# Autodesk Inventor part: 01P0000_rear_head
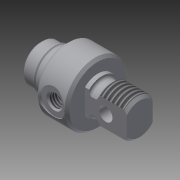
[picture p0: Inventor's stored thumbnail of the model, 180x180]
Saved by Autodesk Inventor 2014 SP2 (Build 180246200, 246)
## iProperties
Created: 2020-01
Part Number: 01P0000_rear_head
Material: Generic
Catalog Web Link: www.cadenas.de
Description: Rear Head-Original Line - Standard Air Cylinders
Vendor: BIMBA
Document SubType Name: Modeling
Designer: psadmin
Manufacturer: BIMBA
Mass: 3.86005 g
Surface Area: 22.3376 cm^2
Volume: 3.86005 cm^3
Density: 1 g/cm^3
Appearance: PSOLRGB-211-211-211
Category: PARTsolutions
Company: BIMBA
Title: 01P0000_rear_head
Author: Cadenas PARTsolutions
Comments: Original Line - Standard Air Cylinders
PSOL_IDENT_0: {$CADENAS_DATA\23d-libs\bimba\bimba_brand\bimba_imperial\bimba_full_line\original_line_cylinders\sta
PSOL_IDENT_1: ndard_air_cylinders\rear_head.prj},239 {VTYP=3D},{NB=01P0000_rear_head},{LINA=01P0000_rear_head},{NN=
PSOL_IDENT_2: Rear Head},{DATE=23.12.2019 10:40:48},{GEOMDATE=15.10.2019 12:00:43},{VERSION=},{LINEID=20},{WBVAR=M
PSOL_IDENT_3: NT,ACTING,DER,Q,T1,T2,T3,T4,TRIM,Y,K,MB,CUSH,FBON},{WBNUMERIC=TRIM,MB,CUSH}  {NB=01P0000_rear_head},
PSOL_IDENT_4: {LINA=01P0000_rear_head},{KT=DUMMY},{PN=01P0000},{BORE=0.43750},{BOREPN=01},{MNT=P},{MNTALG='' , 'Fr
PSOL_IDENT_5: ont Nose' , 'P' , 'Rear Pivot' , 'DX' , 'Double End' , 'BR' , 'Rear Block' , 'BRT' , 'Rear Trunnion'
PSOL_IDENT_6: },{ACTING=},{ACTINGALG= '' , 'Single Acting' },{DER=},{DERALG= '' , 'Standard' },{Q=},{T1=},{T2=},{T
PSOL_IDENT_7: 3=},{T4=},{TRIM=0},{Y=},{K=},{KALG= '', 'without K', 'K', 'with K' },{MB=0},{A1=1.1880},{A1N=0.5000}
PSOL_IDENT_8: ,{A1P=1.1880},{A1B=0.8120},{A1S=0.0000},{A2=0.188},{A2N=0.1880},{A3=0.0200},{D1=0.7380},{D1N=0.4855}
PSOL_IDENT_9: ,{D1P=0.7380},{D1B=0.4855},{D2=0.4465},{C1=0.0300},{C2=0.0300},{NDM=0.1900},{TAB=UNF},{NDMDP=0.2000}
PSOL_IDENT_10: ,{D3=0.1600},{A4=0.1880},{A5=0.3700},{D4=0.0000},{A6=0.0000},{A7=0.5000},{A8=0.1250},{D5=0.4855},{D6=
PSOL_IDENT_11: 0.1875},{A9=0.6250},{NDM2=0.4375},{TAB2=UNF},{C11=0.0300},{C22=0.0000},{C33=0.0300},{C44=0.0300},{A1
PSOL_IDENT_12: 0=0.3095},{A11=0.0000},{NDM3=0.1900},{NDM3N=0.1900},{NDM3B=0.1900},{TAB3=UNF},{TAB3N=UNF},{TAB3B=UNF
PSOL_IDENT_13: },{A12=0.5},{A12N=0.5000},{A12B=0.4680},{A13=0.9380},{D7=0.1590},{D8=0.4350},{A14=0.0500},{A15=0.077
PSOL_IDENT_14: 5},{D9=0.3600},{R1=0.0315},{X1=0.0000},{X2=0.0000},{CX=0.0000},{CC=0.0000},{CON=1},{S1=0.7500},{DB=0
PSOL_IDENT_15: .1562},{X1B=0.2500},{X2B=0.0620},{A8B=0.1250},{A9B=0.5620},{MODEL=1},{NDM4=0.1640},{TAB4=UNC},{NDM4D
PSOL_IDENT_16: P=0.2500},{BC=0.7500},{B1=0.5620},{B2=0.2500},{B3=0.3740},{ON=0},{ON2=1},{G1=0.0000},{G2=0.0000},{G3=
PSOL_IDENT_17: 0.0000},{G4=0.0000},{GD=0.0000},{G5=0.0000},{G6=0.0000},{RON=0},{H1=0.0000},{H2=0.0000},{H3=0.0000},
PSOL_IDENT_18: {H4=0.0000},{H5=0.0000},{H6=0.0000},{F=0.0000},{PNUT=0.7380},{CUSH=0},{CC11=0.000},{CC111=0.0000},{C
PSOL_IDENT_19: C22=0.0000},{CC33=0.0000},{CC44=0.0000},{CC55=0.0000},{CD1=0.0000},{CD2=0.0000},{CD3=0.0000},{CNDM3=
PSOL_IDENT_20: 0.0000},{CTAB3=0.0000},{OLEN=0.9380},{OD=0.2185},{STDIS=0.0000},{STDIS1=0.0000},{BUSHCON=D-8597},{BU
PSOL_IDENT_21: SHL=0.3120},{FBON=0},{LCD=0.0000}
NN: Rear Head
NT: Original Line - Standard Air Cylinders
NB: 01P0000_rear_head
NBSYN: $PN._rear_head
LINA: 01P0000_rear_head
PN: 01P0000
BORE: 0.4375
BOREPN: 01
MNT: Rear Pivot
MNTALG: '' , 'Front Nose' , 'P' , 'Rear Pivot' , 'DX' , 'Double End' , 'BR' , 'Rear Block' , 'BRT' , 'Rear Trunnion'
ACTING: Single Acting
DER: Standard
Q: Without Side Ported Rear Head
T1: without T1
T2: without T2
T3: without T3
T4: without T4
TRIM: 0
Y: without Pivot Bushing
K: without K
MB: 0
A1N: 0.5
A1P: 1.188
A1B: 0.812
A1S: 0
A2N: 0.188
A3: 0.02
D1N: 0.4855
D1P: 0.738
D1B: 0.4855
D2: 0.4465
C1: 0.03
C2: 0.03
TAB: UNF
NDMDP: 0.2
D3: 0.16
A4: 0.188
A5: 0.37
D4: 0
A6: 0
A7: 0.5
A8: 0.125
D5: 0.4855
D6: 0.1875
A9: 0.625
NDM2: 0.4375
TAB2: UNF
C11: 0.03
C22: 0
C33: 0.03
C44: 0.03
A10: 0.3095
A11: 0
NDM3N: 0.19
NDM3B: 0.19
TAB3N: UNF
TAB3B: UNF
A12N: 0.5
A12B: 0.468
A13: 0.938
D7: 0.159
D8: 0.435
A14: 0.05
A15: 0.0775
D9: 0.36
R1: 0.0315
X1: 0
X2: 0
CX: 0
CC: 0
S1: 0.75
DB: 0.1562
X1B: 0.25
X2B: 0.062
A8B: 0.125
A9B: 0.562
NDM4: 0.164
TAB4: UNC
NDM4DP: 0.25
BC: 0.75
B1: 0.562
B2: 0.25
B3: 0.374
G1: 0
G2: 0
G3: 0
G4: 0
GD: 0
G5: 0
G6: 0
H2: 0
H3: 0
F: 0
CUSH: 0
CC111: 0
CC22: 0
CC33: 0
CC44: 0
CC55: 0
CD1: 0
CD2: 0
CD3: 0
CNDM3: 0
CTAB3: 0.0000
OD: 0.2185
STDIS1: 0
BUSHCON: D-8597
BUSHL: 0.312
FBON: 0
LCD: 0
SUPPLIER: BIMBA
ARTICLENO: 01P0000_rear_head
BOMINFO: 01P0000_rear_head
CREATOR: CADENAS GmbH
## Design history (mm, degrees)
sketch "Sketch_8"
  geometry: L1 (17.475, 0)-(0, 0); L2 (0, 0)-(0, 4.909); L3 (0, 4.909)-(0.762, 5.671); L4 (0.762, 5.671)-(3.759, 5.671); L5 (3.759, 5.671)-(4.267, 5.163); L6 (4.267, 5.163)-(4.775, 5.163); L7 (4.775, 5.163)-(4.775, 6.166); L8 (4.775, 6.166)-(7.95, 6.166); L9 (7.95, 6.166)-(7.95, 8.611); L10 (7.95, 8.611)-(8.712, 9.373); L11 (8.712, 9.373)-(16.713, 9.373); L12 (16.713, 9.373)-(17.475, 8.611); L13 (17.475, 8.611)-(17.475, 0); L14 (17.475, 0)-(0, 0)
  constraints: 28 end point
revolve "Revolution1" sketch "Sketch_8" stored, may be unused: angle "d0" = 360 deg
sketch "Sketch_15"
  geometry: L1 (30.175, 0)-(17.475, 0); L2 (17.475, 0)-(17.475, 5.524); L3 (17.475, 5.524)-(18.745, 5.524); L4 (18.745, 5.524)-(18.745, 5.372); L5 (19.545, 4.572)-(20.714, 4.572); L6 (21.217, 4.75)-(21.279, 4.801); L7 (21.279, 4.801)-(22.035, 5.556); L8 (22.035, 5.556)-(29.42, 5.556); L9 (29.42, 5.556)-(30.175, 4.801); L10 (30.175, 4.801)-(30.175, 0); L11 (30.175, 0)-(17.475, 0); A1 r 0.8 centre (19.545, 5.372) between (18.745, 5.372) and (19.545, 4.572); A2 r 0.8 centre (20.714, 5.372) between (20.714, 4.572) and (21.217, 4.75)
  constraints: 22 end point, 4 point on circle, 2 centre point
revolve "Revolution2" sketch "Sketch_15" stored, may be unused: angle "d1" = 360 deg
thread "Thread1" dims "d2" = 7.38444, "d3" = 0
sketch "Sketch_9"
  geometry: L1 (-18.745, -37.49)-(18.745, -37.49); L2 (18.745, -37.49)-(18.745, 37.49); L3 (18.745, 37.49)-(-18.745, 37.49); L4 (-18.745, 37.49)-(-18.745, -37.49); L5 (-3.931, -18.745)-(3.931, -18.745); L6 (3.931, -18.745)-(3.931, 18.745); L7 (3.931, 18.745)-(-3.931, 18.745); L8 (-3.931, 18.745)-(-3.931, -18.745)
  constraints: 16 end point
extrude "Extrusion1" cut sketch "Sketch_9" distance "d4" = 12.7; taper "d5" = 0 deg
sketch "Sketch4"
  geometry: 1 further point
hole "Hole1" sketch "Sketch4" at (0, 0) diameter "d6" = 4.7625; stored, may be unused: countersink angle "d10" = 82 deg, drill point angle "d12" = 120 deg; dims "d7" = 19.05, "d8" = 9.525, "d9" = 6.35, "d11" = 17.4625
sketch "Sketch_16"
  geometry: L1 (-12.7, 9.373)-(-12.7, 0); L2 (-12.7, 0)-(-14.684, 0); L3 (-14.684, 0)-(-14.684, 7.927); L4 (-14.684, 7.927)-(-15.113, 8.357); L5 (-15.113, 8.357)-(-16.662, 8.357); L6 (-16.662, 8.357)-(-16.662, 9.373); L7 (-16.662, 9.373)-(-12.7, 9.373); L8 (-12.7, 9.373)-(-12.7, 0)
  constraints: 16 end point
revolve "Revolution3" sketch "Sketch_16" stored, may be unused: angle "d13" = 360 deg
thread "Thread2" dims "d14" = 5.54609, "d15" = 0
sketch "Sketch_24"
  geometry: L1 (4.775, 0)-(4.267, 0); L2 (4.066, 6.166)-(4.066, 6.082); L3 (4.066, 6.082)-(4.664, 5.485); L4 (4.664, 5.305)-(4.521, 5.163); L5 (4.521, 5.163)-(4.267, 5.163); L6 (4.267, 5.163)-(4.267, 4.909); L7 (4.267, 4.909)-(4.775, 4.909); L8 (4.775, 4.909)-(4.775, 5.66); L9 (4.775, 5.66)-(4.27, 6.166); L10 (4.27, 6.166)-(4.066, 6.166); A1 r 0.127 centre (4.574, 5.395) between (4.664, 5.305) and (4.664, 5.485)
  constraints: 20 end point, 2 point on circle, 1 centre point
revolve "Revolution4" sketch "Sketch_24" stored, may be unused: angle "d16" = 360 deg
sketch "Sketch_43"
  geometry: C1 r 2.019 at (23.825, 0); 1 further point
  constraints: 1 centre point
extrude "Extrusion2" cut sketch "Sketch_43" stored distance "d17" = 11.79195; taper "d18" = 0 deg
node "1_XY"
node "1_YZ"
node "1_ZX"
node "1_X"
node "1_Y"
node "1_Z"
node "1_Center"
node "c1_XY"
node "c1_YZ"
node "c1_ZX"
node "c1_X"
node "c1_Y"
node "c1_Z"
node "c1_Center"
node "c2_XY"
node "c2_YZ"
node "c2_ZX"
node "c2_X"
node "c2_Y"
node "c2_Z"
node "c2_Center"
node "cc1_XY"
node "cc1_YZ"
node "cc1_ZX"
node "cc1_X"
node "cc1_Y"
node "cc1_Z"
node "cc1_Center"
node "cc2_XY"
node "cc2_YZ"
node "cc2_ZX"
node "cc2_X"
node "cc2_Y"
node "cc2_Z"
node "cc2_Center"
node "lovra1_XY"
node "lovra1_YZ"
node "lovra1_ZX"
node "lovra1_X"
node "lovra1_Y"
node "lovra1_Z"
node "lovra1_Center"
node "lovra2_XY"
node "lovra2_YZ"
node "lovra2_ZX"
node "lovra2_X"
node "lovra2_Y"
node "lovra2_Z"
node "lovra2_Center"
node "lovra21_XY"
node "lovra21_YZ"
node "lovra21_ZX"
node "lovra21_X"
node "lovra21_Y"
node "lovra21_Z"
node "lovra21_Center"
node "lovra22_XY"
node "lovra22_YZ"
node "lovra22_ZX"
node "lovra22_X"
node "lovra22_Y"
node "lovra22_Z"
node "lovra22_Center"
node "lovra3_XY"
node "lovra3_YZ"
node "lovra3_ZX"
node "lovra3_X"
node "lovra3_Y"
node "lovra3_Z"
node "lovra3_Center"
node "olen_XY"
node "olen_YZ"
node "olen_ZX"
node "olen_X"
node "olen_Y"
node "olen_Z"
node "olen_Center"
node "p1_XY"
node "p1_YZ"
node "p1_ZX"
node "p1_X"
node "p1_Y"
node "p1_Z"
node "p1_Center"
node "p2_XY"
node "p2_YZ"
node "p2_ZX"
node "p2_X"
node "p2_Y"
node "p2_Z"
node "p2_Center"
node "port_XY"
node "port_YZ"
node "port_ZX"
node "port_X"
node "port_Y"
node "port_Z"
node "port_Center"
node "port2_XY"
node "port2_YZ"
node "port2_ZX"
node "port2_X"
node "port2_Y"
node "port2_Z"
node "port2_Center"
node "thd1_XY"
node "thd1_YZ"
node "thd1_ZX"
node "thd1_X"
node "thd1_Y"
node "thd1_Z"
node "thd1_Center"
node "thd2_XY"
node "thd2_YZ"
node "thd2_ZX"
node "thd2_X"
node "thd2_Y"
node "thd2_Z"
node "thd2_Center"
node "to_mounting_bracket_XY"
node "to_mounting_bracket_YZ"
node "to_mounting_bracket_ZX"
node "to_mounting_bracket_X"
node "to_mounting_bracket_Y"
node "to_mounting_bracket_Z"
node "to_mounting_bracket_Center"
node "to_nut_XY"
node "to_nut_YZ"
node "to_nut_ZX"
node "to_nut_X"
node "to_nut_Y"
node "to_nut_Z"
node "to_nut_Center"
node "to_pin_XY"
node "to_pin_YZ"
node "to_pin_ZX"
node "to_pin_X"
node "to_pin_Y"
node "to_pin_Z"
node "to_pin_Center"
node "to_screw_XY"
node "to_screw_YZ"
node "to_screw_ZX"
node "to_screw_X"
node "to_screw_Y"
node "to_screw_Z"
node "to_screw_Center"
node "to_tube_XY"
node "to_tube_YZ"
node "to_tube_ZX"
node "to_tube_X"
node "to_tube_Y"
node "to_tube_Z"
node "to_tube_Center"
body "Solid1"
other parameters: "d19" = 0, "d20" = 0, "d21" = 0, "d22" = 0, "d23" = 0, "d24" = 0
